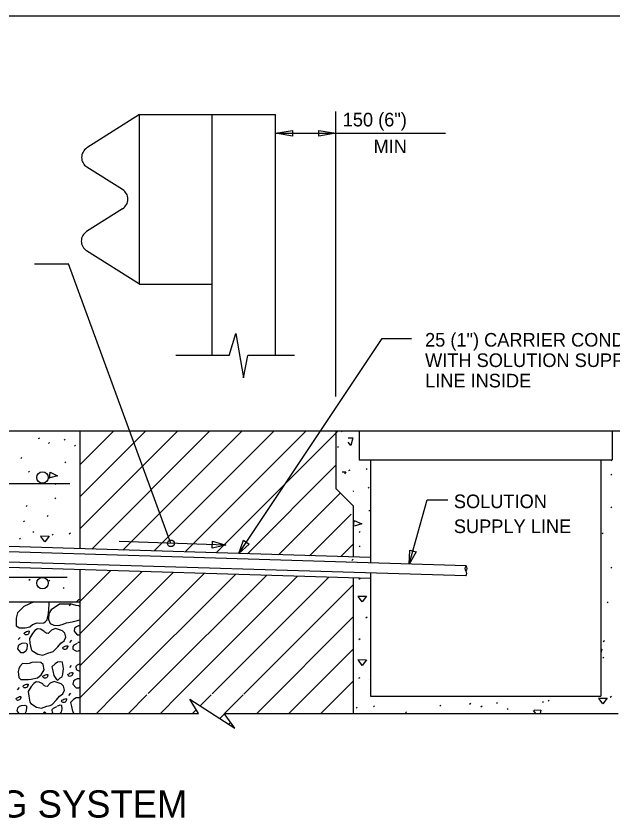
# Model space of a CAD drawing. Extents: x 3239 to 4230, y -4276 to -2494.
# Drawn here: x 3601.5 to 3733.1, y -3280.1 to -3103.3 of the extents above; entities that cross this region are included whole.
import ezdxf

# ---------------------------------------------------------------- set-up
doc = ezdxf.new("R2010")
doc.units = 0
doc.layers.add('2', color=7, linetype='Continuous')

msp = doc.modelspace()

# ---------------------------------------------------------------- linework, layer by layer
at = {"layer": '2'}
for p, q in [((4065.03, -3103.29), (3279.03, -3103.29)), ((3672.03, -3154.89), (3672.03, -3124.37)), ((3628.72, -3125.03), (3617.12, -3132.37)), ((3628.72, -3125.03), (3658.71, -3125.03)), ((3628.72, -3162.42), (3628.72, -3125.03)), ((3644.71, -3178.13), (3644.71, -3125.03)), ((3658.71, -3178.13), (3658.71, -3125.03)), ((3658.71, -3129.13), (3696.16, -3129.13)), ((3624.98, -3141.56), (3617.12, -3136.59)), ((3624.98, -3145.79), (3617.04, -3150.81)), ((3628.72, -3162.42), (3617.04, -3155.03)), ((3672.03, -3187.19), (3672.03, -3154.89)), ((3605.54, -3157.92), (3613.09, -3157.92)), ((3635.65, -3219.56), (3613.09, -3157.92)), ((3628.72, -3162.42), (3644.71, -3162.42)), ((3648.51, -3178.13), (3636.71, -3178.13)), ((3662.88, -3178.13), (3652.6, -3178.13)), ((3407.28, -3194.76), (3615.58, -3194.76)), ((3615.58, -3194.76), (3672.03, -3194.76)), ((3615.58, -3202.22), (3623.04, -3194.76)), ((3615.58, -3209.29), (3630.11, -3194.76)), ((3615.58, -3216.36), (3637.18, -3194.76)), ((3615.58, -3194.76), (3615.58, -3220.74)), ((3618.19, -3220.82), (3644.25, -3194.76)), ((3625.06, -3221.03), (3651.32, -3194.76)), ((3631.92, -3221.23), (3658.39, -3194.76)), ((3638.78, -3221.44), (3665.46, -3194.76)), ((3645.64, -3221.65), (3672.54, -3194.76)), ((3672.03, -3194.76), (3677.13, -3194.76)), ((3672.03, -3194.76), (3672.03, -3207.46)), ((3673.27, -3194.94), (3673.5, -3194.75)), ((3677.13, -3194.76), (3677.13, -3201.16)), ((3677.13, -3194.76), (3677.13, -3196.06)), ((3677.13, -3194.76), (3732.93, -3194.76)), ((3732.93, -3194.76), (3738.03, -3194.76)), ((3732.93, -3194.76), (3732.93, -3199.86)), ((3606.48, -3196.46), (3606.71, -3196.27)), ((3612.08, -3196.77), (3612.32, -3196.58)), ((3608.67, -3197.54), (3608.9, -3197.35)), ((3614.41, -3198.1), (3614.64, -3197.92)), ((3672.36, -3198.36), (3672.6, -3198.17)), ((3732.93, -3199.86), (3732.93, -3201.16)), ((3602.57, -3200.84), (3602.8, -3200.65)), ((3612.22, -3201.8), (3612.46, -3201.61)), ((3677.13, -3201.16), (3679.63, -3201.16)), ((3679.63, -3201.16), (3730.43, -3201.16)), ((3679.63, -3201.16), (3679.63, -3223.89)), ((3730.43, -3201.16), (3732.93, -3201.16)), ((3730.43, -3201.16), (3730.43, -3253.26)), ((3732.68, -3201.35), (3732.91, -3201.16)), ((3604.21, -3203.8), (3604.44, -3203.62)), ((3652.51, -3221.86), (3672.03, -3202.34)), ((3674.9, -3203.51), (3675.14, -3203.32)), ((3678.68, -3203.23), (3678.91, -3203.04)), ((3732.63, -3204.52), (3732.86, -3204.33)), ((3424.79, -3206.33), (3613.33, -3206.33)), ((3610.1, -3206.53), (3610.34, -3206.34)), ((3672.03, -3207.46), (3675.83, -3211.26)), ((3679.14, -3207.37), (3679.37, -3207.19)), ((3659.37, -3222.07), (3673, -3208.44)), ((3675.83, -3208.07), (3675.96, -3207.96)), ((3610.06, -3209.7), (3610.29, -3209.51)), ((3603.7, -3211.42), (3603.93, -3211.24)), ((3675.83, -3211.26), (3675.83, -3222.57)), ((3679.28, -3212.41), (3679.51, -3212.22)), ((3732.61, -3211.67), (3732.85, -3211.48)), ((3603.11, -3214.82), (3603.34, -3214.63)), ((3608.35, -3213.61), (3608.59, -3213.43)), ((3615.53, -3213.31), (3615.58, -3213.27)), ((3666.23, -3222.28), (3675.38, -3213.13)), ((3700.7, -3224.53), (3434.16, -3216.42)), ((3679.63, -3222.69), (3434.26, -3215.22)), ((3605.18, -3217.12), (3605.41, -3216.93)), ((3609.47, -3217.71), (3609.7, -3217.52)), ((3613.24, -3217.43), (3613.48, -3217.25)), ((3677.16, -3217.14), (3677.39, -3216.95)), ((3730.7, -3217.43), (3730.93, -3217.24)), ((3679.63, -3227.32), (3433.7, -3219.84)), ((3700.64, -3226.76), (3433.79, -3218.64)), ((3602.25, -3218.6), (3602.48, -3218.42)), ((3647.77, -3219.96), (3624.23, -3219.18)), ((3673.09, -3222.49), (3675.83, -3219.75)), ((3677.11, -3220.3), (3677.35, -3220.12)), ((3675.51, -3223.35), (3675.83, -3223.04)), ((3732.64, -3224.97), (3732.87, -3224.78)), ((3380.06, -3227.04), (3612.77, -3227.04)), ((3615.58, -3225.37), (3615.58, -3257.06)), ((3615.58, -3232.41), (3622.4, -3225.58)), ((3615.58, -3239.48), (3629.27, -3225.79)), ((3620.05, -3242.08), (3636.13, -3226)), ((3620.08, -3249.11), (3642.99, -3226.2)), ((3623.29, -3252.98), (3649.85, -3226.41)), ((3630.65, -3252.69), (3656.72, -3226.62)), ((3637.35, -3253.06), (3663.58, -3226.83)), ((3644.71, -3252.77), (3670.44, -3227.04)), ((3679.63, -3226.12), (3679.63, -3253.26)), ((3604.35, -3227.67), (3604.59, -3227.49)), ((3608.74, -3227.89), (3608.97, -3227.7)), ((3651.74, -3252.81), (3675.83, -3228.72)), ((3675.83, -3227.2), (3675.83, -3257.06)), ((3677.1, -3227.45), (3677.33, -3227.27)), ((3611.91, -3229.47), (3612.14, -3229.28)), ((3380.06, -3232.44), (3615.58, -3232.44)), ((3731.82, -3232.63), (3732.05, -3232.45)), ((3654.56, -3257.06), (3675.83, -3235.79)), ((3678.64, -3235.98), (3678.87, -3235.79)), ((3677.1, -3240.74), (3677.33, -3240.56)), ((3730.97, -3241.19), (3731.2, -3241.01)), ((3615.58, -3246.55), (3620.2, -3241.92)), ((3661.63, -3257.06), (3675.83, -3242.87)), ((3730.87, -3244.87), (3731.11, -3244.69)), ((3615.58, -3253.62), (3620.2, -3248.99)), ((3668.7, -3257.06), (3675.83, -3249.94)), ((3677.1, -3249.3), (3677.33, -3249.11)), ((3679.57, -3249.59), (3679.63, -3249.54)), ((3619.21, -3257.06), (3623.26, -3253)), ((3626.28, -3257.06), (3630.34, -3253)), ((3633.35, -3257.06), (3637.41, -3253)), ((3642.09, -3255.39), (3644.48, -3253)), ((3647.49, -3257.06), (3651.55, -3253)), ((3679.63, -3253.26), (3730.43, -3253.26)), ((3732.5, -3253.45), (3732.74, -3253.26)), ((3641.73, -3257.06), (3639.83, -3253.94)), ((3639.83, -3253.94), (3649.7, -3260.31)), ((3694.95, -3255.45), (3695.18, -3255.27)), ((3701.5, -3255.01), (3701.73, -3254.82)), ((3707.41, -3254.82), (3707.65, -3254.64)), ((3717.55, -3254.61), (3717.78, -3254.43)), ((3718.81, -3254.33), (3719.04, -3254.15)), ((3515.43, -3257.06), (3641.73, -3257.06)), ((3640.42, -3257.06), (3641.23, -3256.25)), ((3647.4, -3257.06), (3675.83, -3257.06)), ((3649.7, -3260.31), (3647.4, -3257.06)), ((3675.83, -3257.06), (3734.23, -3257.06)), ((3676.49, -3255.88), (3676.73, -3255.69)), ((3680.27, -3255.6), (3680.5, -3255.41)), ((3687.37, -3256.91), (3687.61, -3256.72)), ((3704, -3255.6), (3704.24, -3255.41)), ((3709.74, -3256.16), (3709.97, -3255.97)), ((3646.39, -3258.17), (3647.44, -3257.12)), ((3648.38, -3259.45), (3648.8, -3259.03))]:
    msp.add_line(p, q, dxfattribs=at)
for points in [[(3662.46, -3129.76), (3658.71, -3129.13), (3662.46, -3128.5)], [(3668.28, -3128.5), (3672.03, -3129.13), (3668.28, -3129.76)], [(3644.79, -3219.11), (3647.77, -3219.96), (3644.74, -3220.61)], [(3652.89, -3219.72), (3650.6, -3221.81), (3651.64, -3218.89)], [(3689.72, -3221.46), (3688.2, -3224.15), (3688.28, -3221.06)]]:
    msp.add_lwpolyline(points, close=True, dxfattribs=at)
for points in [[(3648.51, -3178.13), (3649.98, -3173.3), (3651.62, -3183.06), (3652.6, -3178.13)], [(3650.6, -3221.81), (3682.18, -3174.42), (3688.65, -3174.42)], [(3674.73, -3196.27), (3675.72, -3196.32), (3675.32, -3198.02), (3674.73, -3197.23)], [(3608.87, -3205.25), (3609.01, -3203.9), (3610.64, -3204.64), (3608.98, -3205.13)], [(3673.42, -3203.76), (3674.23, -3203.77), (3673.88, -3204.22)], [(3688.2, -3224.15), (3692.16, -3209.94), (3696.7, -3209.94)], [(3675.92, -3215.85), (3676.06, -3214.5), (3677.7, -3215.25), (3676.04, -3215.74)], [(3606.86, -3217.94), (3608.8, -3217.97), (3607.82, -3219.23), (3607, -3218.08)], [(3614.78, -3232.44), (3614.81, -3232.46), (3615.36, -3231.95), (3615.58, -3231.86)], [(3676.82, -3231.18), (3678.75, -3231.2), (3677.78, -3232.46), (3676.96, -3231.32)], [(3605.4, -3232.44), (3603.25, -3233.52), (3601.84, -3234.86), (3601.52, -3236.09), (3601.51, -3237.77), (3602.28, -3238.16), (3603.51, -3238.18), (3604.56, -3237.96), (3605.1, -3237.45), (3606.13, -3237.06), (3606.6, -3237.17), (3607.64, -3237.08), (3607.93, -3236.9), (3608.34, -3236.41), (3608.68, -3235.03), (3608.75, -3234.11), (3608.81, -3233.03), (3608.77, -3232.6), (3608.64, -3232.44)], [(3613.36, -3232.94), (3611.09, -3232.98), (3609.24, -3234.21), (3608.7, -3235.02), (3608.67, -3236.38), (3609.05, -3237.26), (3609.84, -3237.63), (3610.89, -3237.69), (3611.64, -3237.47), (3612.65, -3237.1), (3613.85, -3236.84), (3615.03, -3236.58), (3615.58, -3236.42)], [(3615.58, -3233.56), (3615.35, -3233.37), (3614.74, -3233.28), (3613.51, -3232.93), (3613.2, -3233.37)], [(3608.3, -3239.44), (3607.82, -3239.18), (3607.64, -3238.89), (3606.87, -3238.5), (3606.25, -3238.4), (3605.67, -3238.76), (3605.12, -3239.41), (3604.48, -3240.54), (3604.57, -3241.57), (3604.84, -3242.92), (3605.01, -3243.19), (3606.28, -3244), (3607.37, -3244.21), (3608.53, -3243.8), (3609.27, -3243.58), (3609.71, -3243.39), (3610.68, -3242.41), (3611.37, -3241.59), (3612.08, -3241.07), (3612.45, -3240.27), (3612.22, -3239.4), (3611.74, -3238.83), (3610.17, -3238.36), (3609.31, -3238.74), (3608.6, -3239.41), (3608.45, -3239.43)], [(3615.58, -3237.73), (3615.26, -3237.76), (3614.82, -3237.95), (3614.41, -3238.29), (3614.31, -3238.91), (3614.98, -3239.75), (3615.28, -3239.72), (3615.58, -3239.7)], [(3602.39, -3240.3), (3601.98, -3240.79)], [(3613.73, -3240.93), (3613.31, -3241.42)], [(3603.55, -3241.6), (3602.79, -3241.66), (3602.35, -3241.86), (3601.94, -3242.19), (3601.84, -3242.81), (3602.51, -3243.65), (3602.81, -3243.62), (3603.11, -3243.6), (3603.69, -3243.26), (3603.83, -3243.1), (3603.96, -3242.78), (3604.05, -3242.16), (3604.03, -3241.86), (3603.86, -3241.72), (3603.7, -3241.58)], [(3614.99, -3241.62), (3614.26, -3241.99), (3613.99, -3242.32), (3614.04, -3242.92), (3614.52, -3243.19), (3614.84, -3243.31), (3615.29, -3243.27), (3615.58, -3243.15)], [(3615.58, -3241.34), (3615.43, -3241.43), (3615.13, -3241.46)], [(3730.43, -3242.92), (3730.61, -3242.93), (3730.43, -3243.73)], [(3603.82, -3246.13), (3602.89, -3246.06), (3602.34, -3246.72), (3602.08, -3247.2), (3601.98, -3247.81), (3602.1, -3249.16), (3602.59, -3249.57), (3604.25, -3249.58), (3604.85, -3249.53), (3606.2, -3249.25), (3607.04, -3248.57), (3607.7, -3247.47), (3607.45, -3246.27), (3606.95, -3245.85), (3605.9, -3245.79), (3604.99, -3245.87), (3604.4, -3246.08), (3603.82, -3246.13)], [(3611.4, -3245.72), (3610.64, -3245.78), (3610.09, -3246.14), (3609.38, -3246.79), (3609.61, -3247.68), (3609.86, -3248.71), (3610.39, -3249.58), (3610.7, -3249.7), (3611.25, -3249.2), (3611.69, -3249.01), (3611.79, -3248.41), (3611.99, -3247.17), (3611.72, -3245.84), (3611.55, -3245.71)], [(3613.68, -3246.47), (3613.26, -3246.96)], [(3615.58, -3246.1), (3614.96, -3246.42), (3614.68, -3246.75), (3614.74, -3247.35), (3615.22, -3247.61), (3615.53, -3247.74), (3615.58, -3247.74)], [(3676.82, -3245.2), (3678.75, -3245.23), (3677.78, -3246.48), (3676.96, -3245.34)], [(3615.58, -3249.41), (3615, -3249.46), (3614.56, -3249.65), (3614.13, -3249.97), (3614.03, -3250.59), (3614.72, -3251.44), (3615.02, -3251.42), (3615.32, -3251.39), (3615.58, -3251.23)], [(3602.18, -3251.34), (3601.77, -3251.84)], [(3608.04, -3251.11), (3607.56, -3250.85), (3607.38, -3250.56), (3606.59, -3250.19), (3605.97, -3250.1), (3605.41, -3250.45), (3604.86, -3251.09), (3604.19, -3252.21), (3604.29, -3253.27), (3604.55, -3254.6), (3604.73, -3254.89), (3606.02, -3255.67), (3607.08, -3255.88), (3608.27, -3255.47), (3608.99, -3255.28), (3609.43, -3255.09), (3610.42, -3254.09), (3611.11, -3253.26), (3611.8, -3252.74), (3612.19, -3251.97), (3611.96, -3251.07), (3611.45, -3250.51), (3609.91, -3250.06), (3609.03, -3250.42), (3608.34, -3251.09), (3608.19, -3251.1)], [(3613.47, -3252.6), (3613.05, -3253.09)], [(3603.41, -3255.29), (3602.65, -3255.36), (3602.21, -3255.55), (3601.8, -3255.89), (3601.7, -3256.51), (3602.14, -3257.06)], [(3603.37, -3257.06), (3603.55, -3256.96), (3603.69, -3256.79), (3603.82, -3256.48), (3603.91, -3255.86), (3603.89, -3255.55), (3603.72, -3255.42), (3603.56, -3255.28)], [(3611.11, -3257.06), (3611.13, -3257.05), (3611.54, -3256.71), (3611.64, -3256.09), (3611.57, -3255.34), (3611.13, -3255.22), (3610.84, -3255.4), (3610.53, -3255.43)], [(3615.51, -3253.59), (3614.75, -3253.66), (3614.2, -3254.01), (3613.49, -3254.66), (3613.72, -3255.56), (3613.97, -3256.58), (3614.26, -3257.06)], [(3729.9, -3253.68), (3731.84, -3253.7), (3730.86, -3254.96), (3730.04, -3253.82)], [(3608.16, -3257.06), (3607.77, -3256.74), (3607.5, -3257.06)], [(3610.39, -3255.59), (3609.66, -3255.96), (3609.39, -3256.29), (3609.44, -3256.89), (3609.74, -3257.06)], [(3615.38, -3257.06), (3615.58, -3256.97)], [(3716.06, -3257.06), (3715.59, -3256.42)], [(3715.73, -3256.28), (3717.19, -3256.35), (3717.03, -3257.06)]]:
    msp.add_lwpolyline(points, dxfattribs=at)
for centre, radius in [((3607.34, -3205.05), 1.25), ((3635.65, -3219.56), 0.731), ((3607.34, -3228.33), 1.25)]:
    msp.add_circle(centre, radius, dxfattribs=at)
for centre, radius, start, end in [((3618.45, -3134.48), 2.5, 122.3108, 237.6892), ((3623.64, -3143.67), 2.5, 302.3108, 57.6892), ((3618.38, -3152.92), 2.5, 122.3108, 237.6892), ((3701.24, -3225.1), 0.788, 133.2582, 223.2582), ((3700.13, -3225.07), 0.788, 313.2582, 43.2582), ((3700, -3226.18), 0.858, 317.7334, 38.7831)]:
    msp.add_arc(centre, radius, start, end, dxfattribs=at)
for points in [[(3604.32, -3239.29), (3604.25, -3239.49), (3604.09, -3239.63), (3603.67, -3239.76), (3603.41, -3239.58), (3603.3, -3239.33), (3603.57, -3239.18), (3604.09, -3238.89), (3604.4, -3238.95), (3604.33, -3239.31)], [(3612.8, -3242.51), (3612.73, -3242.71), (3612.57, -3242.88), (3612.14, -3242.98), (3611.89, -3242.83), (3611.8, -3242.58), (3612.07, -3242.4), (3612.57, -3242.14), (3612.88, -3242.18), (3612.8, -3242.53)], [(3613.93, -3248.42), (3613.86, -3248.63), (3613.7, -3248.77), (3613.28, -3248.9), (3613.02, -3248.72), (3612.91, -3248.47), (3613.18, -3248.31), (3613.7, -3248.03), (3614.01, -3248.09), (3613.91, -3248.45)], [(3608.43, -3248.84), (3608.36, -3249.04), (3608.2, -3249.19), (3607.77, -3249.31), (3607.52, -3249.14), (3607.41, -3248.89), (3607.68, -3248.73), (3608.2, -3248.45), (3608.51, -3248.51), (3608.41, -3248.87)], [(3604.06, -3250.96), (3603.99, -3251.18), (3603.83, -3251.33), (3603.39, -3251.45), (3603.15, -3251.28), (3603.04, -3251.03), (3603.31, -3250.85), (3603.83, -3250.59), (3604.14, -3250.63), (3604.04, -3250.98)], [(3602.51, -3253.72), (3602.44, -3253.92), (3602.28, -3254.07), (3601.85, -3254.19), (3601.6, -3254.01), (3601.49, -3253.76), (3601.76, -3253.61), (3602.28, -3253.32), (3602.59, -3253.38), (3602.49, -3253.74)], [(3612.54, -3254.21), (3612.47, -3254.41), (3612.31, -3254.55), (3611.88, -3254.68), (3611.63, -3254.5), (3611.52, -3254.25), (3611.79, -3254.1), (3612.31, -3253.81), (3612.62, -3253.87), (3612.52, -3254.23)]]:
    msp.add_spline(points, degree=3, dxfattribs=at)

# ---------------------------------------------------------------- texts
for s, height, p in [('150 (6")', 3, (3673.52, -3127.63)), ('MIN', 3, (3680.31, -3133.52)), ('25 (1") CARRIER CONDUIT', 3, (3691.67, -3176.18)), ('WITH SOLUTION SUPPLY', 3, (3691.67, -3180.68)), ('LINE INSIDE', 3, (3691.67, -3185.18)), ('SOLUTION', 3, (3698.02, -3211.8)), ('SUPPLY LINE', 3, (3698.02, -3217.3)), ('INSTALLATION OF SPRAY DISK FOR ANTI-ICING SYSTEM ', 6, (3418.58, -3280.03))]:
    msp.add_text(s, height=height, dxfattribs=at).set_placement(p)

doc.saveas('drawing.dxf')
